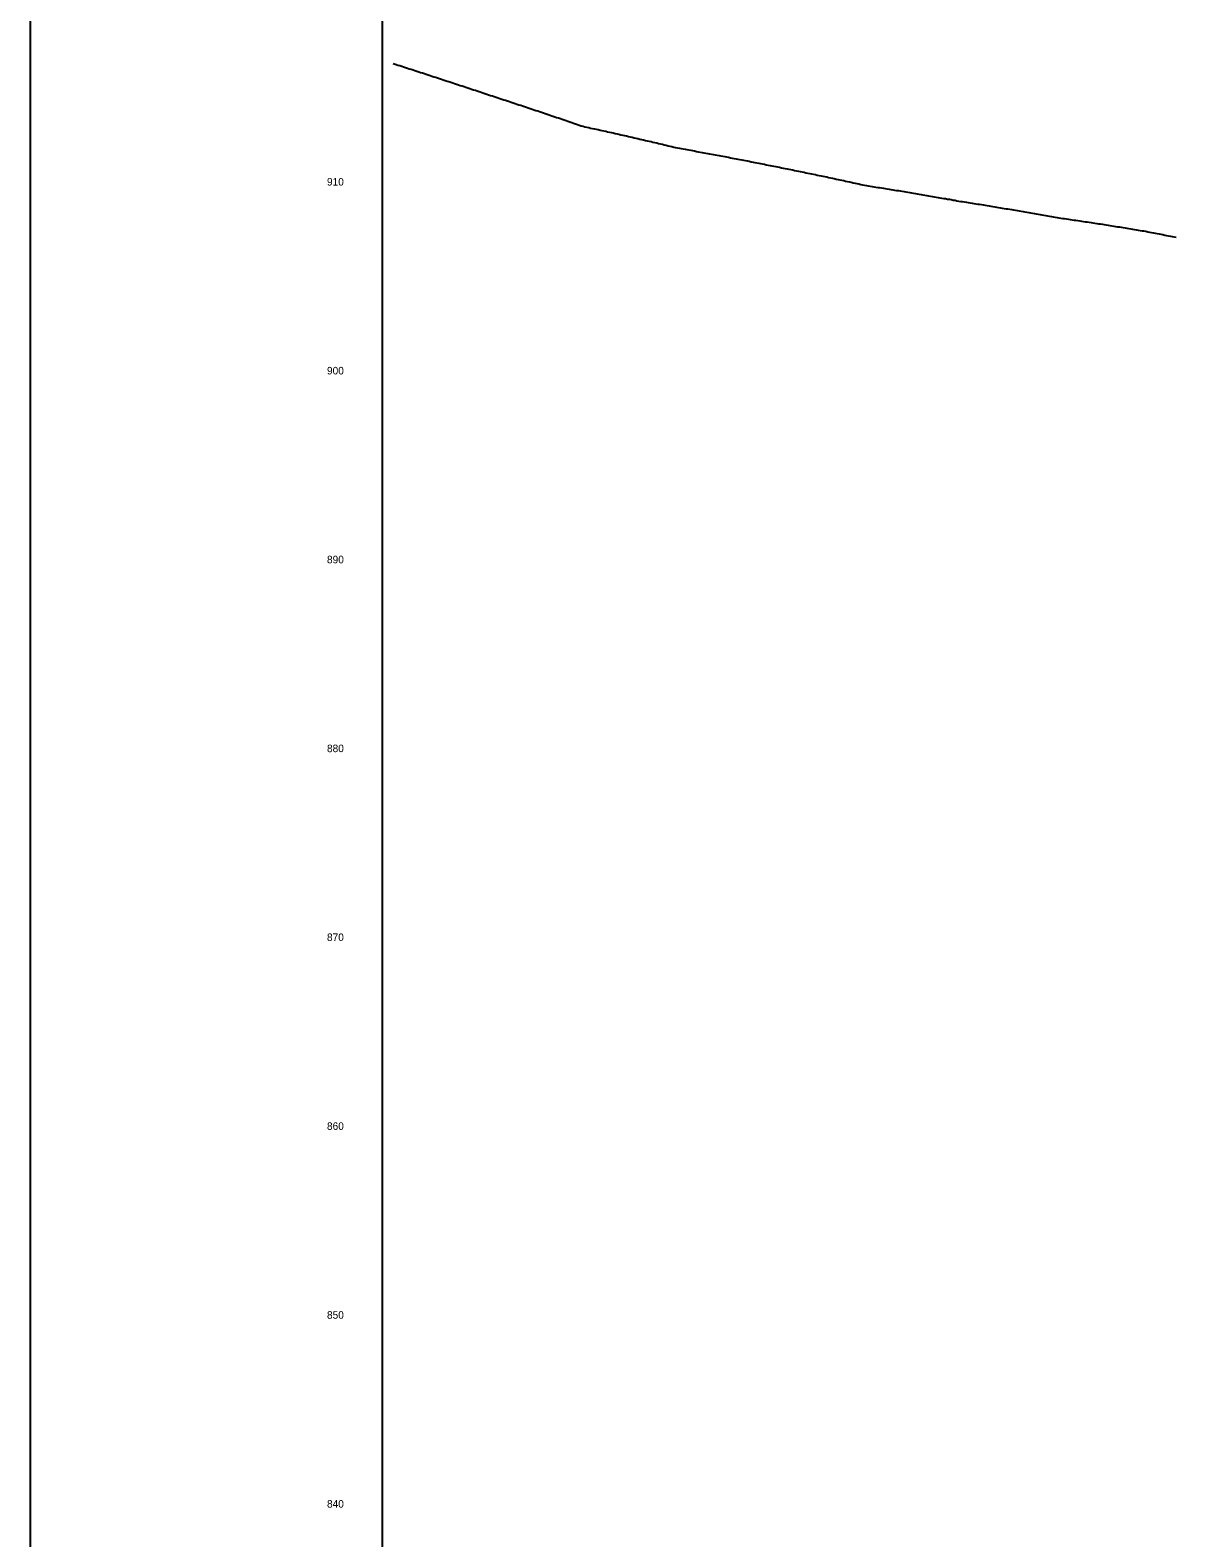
# Model space of a CAD drawing. Extents: x 1738393 to 1742179, y 1214897 to 1219897.
# Drawn here: x 1738393 to 1738999, y 1217783 to 1218581 of the extents above; entities that cross this region are included whole.
import ezdxf

# ---------------------------------------------------------------- set-up
doc = ezdxf.new("R2010")
doc.units = 0
for name, color, linetype in [('Default', 7, 'Continuous'), ('RD_DDB_ElevTX', 7, 'Continuous'), ('RD_DDB_Profile_EX', 7, 'Continuous'), ('RD_Sketch8', 7, 'Continuous')]:
    doc.layers.add(name, color=color, linetype=linetype)

msp = doc.modelspace()

# ---------------------------------------------------------------- linework, layer by layer
at = {"layer": 'Default'}
msp.add_line((1738579.37, 1217396.76), (1738579.37, 1219896.76), dxfattribs=at)
at = {"layer": 'RD_DDB_Profile_EX'}
for points in [[(1738585.11, 1218563.4), (1738585.58, 1218563.25), (1738586.58, 1218562.92), (1738587.58, 1218562.6), (1738588.58, 1218562.27), (1738589.58, 1218561.95), (1738590.58, 1218561.62), (1738591.58, 1218561.3), (1738592.58, 1218560.97), (1738593.58, 1218560.64), (1738594.58, 1218560.32), (1738595.58, 1218559.99), (1738596.58, 1218559.67), (1738597.58, 1218559.34), (1738598.58, 1218559.02), (1738599.58, 1218558.69), (1738600.58, 1218558.37), (1738601.58, 1218558.04), (1738602.58, 1218557.71), (1738603.58, 1218557.39), (1738604.58, 1218557.06), (1738605.58, 1218556.73), (1738606.58, 1218556.41), (1738607.58, 1218556.08), (1738608.58, 1218555.75), (1738609.58, 1218555.43), (1738610.58, 1218555.1), (1738611.58, 1218554.77), (1738612.58, 1218554.44), (1738613.58, 1218554.11), (1738614.58, 1218553.79), (1738615.58, 1218553.46), (1738616.58, 1218553.13), (1738617.58, 1218552.8), (1738618.58, 1218552.48), (1738619.58, 1218552.15), (1738620.58, 1218551.82), (1738621.58, 1218551.49), (1738622.58, 1218551.17), (1738623.58, 1218550.84), (1738624.58, 1218550.51), (1738625.58, 1218550.18), (1738626.58, 1218549.85), (1738627.58, 1218549.53), (1738628.58, 1218549.2), (1738629.58, 1218548.87), (1738630.58, 1218548.54), (1738631.58, 1218548.2), (1738632.58, 1218547.86), (1738633.58, 1218547.52), (1738634.58, 1218547.18), (1738635.58, 1218546.84), (1738636.58, 1218546.52), (1738637.58, 1218546.19), (1738638.58, 1218545.87), (1738639.58, 1218545.54), (1738640.58, 1218545.22), (1738641.58, 1218544.89), (1738642.58, 1218544.56), (1738643.58, 1218544.24), (1738644.58, 1218543.91), (1738645.58, 1218543.58), (1738646.58, 1218543.25), (1738647.58, 1218542.92), (1738648.58, 1218542.59), (1738649.58, 1218542.26), (1738650.58, 1218541.93), (1738651.58, 1218541.6), (1738652.58, 1218541.27), (1738653.58, 1218540.93), (1738654.58, 1218540.6), (1738655.58, 1218540.27), (1738656.58, 1218539.94), (1738657.58, 1218539.6), (1738658.58, 1218539.27), (1738659.58, 1218538.93), (1738660.58, 1218538.6), (1738661.58, 1218538.26), (1738662.58, 1218537.93), (1738663.58, 1218537.59), (1738664.58, 1218537.26), (1738665.58, 1218536.92), (1738666.58, 1218536.58), (1738667.58, 1218536.24), (1738668.58, 1218535.9), (1738669.58, 1218535.57), (1738670.58, 1218535.23), (1738671.58, 1218534.89), (1738672.58, 1218534.55), (1738673.58, 1218534.21), (1738674.58, 1218533.87), (1738675.58, 1218533.52), (1738676.58, 1218533.18), (1738677.58, 1218532.84), (1738678.58, 1218532.5), (1738679.58, 1218532.15), (1738680.58, 1218531.81), (1738681.58, 1218531.47), (1738682.58, 1218531.12), (1738683.58, 1218530.78), (1738684.58, 1218530.43)], [(1738684.58, 1218530.43), (1738685.58, 1218530.13), (1738686.58, 1218529.89), (1738687.58, 1218529.68), (1738688.58, 1218529.46), (1738689.58, 1218529.24), (1738690.58, 1218529.03), (1738691.58, 1218528.81), (1738692.58, 1218528.59), (1738693.58, 1218528.37), (1738694.58, 1218528.15), (1738695.58, 1218527.93), (1738696.58, 1218527.71), (1738697.58, 1218527.49), (1738698.58, 1218527.27), (1738699.58, 1218527.05), (1738700.58, 1218526.82), (1738701.58, 1218526.6), (1738702.58, 1218526.38), (1738703.58, 1218526.15), (1738704.58, 1218525.93), (1738705.58, 1218525.7), (1738706.58, 1218525.48), (1738707.58, 1218525.25), (1738708.58, 1218525.03), (1738709.58, 1218524.8), (1738710.58, 1218524.56), (1738711.58, 1218524.32), (1738712.58, 1218524.09), (1738713.58, 1218523.86), (1738714.58, 1218523.63), (1738715.58, 1218523.4), (1738716.58, 1218523.17), (1738717.58, 1218522.94), (1738718.58, 1218522.71), (1738719.58, 1218522.48), (1738720.58, 1218522.24), (1738721.58, 1218522.01), (1738722.58, 1218521.78), (1738723.58, 1218521.54), (1738724.58, 1218521.31), (1738725.58, 1218521.07), (1738726.58, 1218520.84), (1738727.58, 1218520.6), (1738728.58, 1218520.36), (1738729.58, 1218520.13), (1738730.58, 1218519.89), (1738731.58, 1218519.65), (1738732.58, 1218519.41), (1738733.58, 1218519.17), (1738734.58, 1218518.93), (1738735.58, 1218518.7), (1738736.58, 1218518.51), (1738737.58, 1218518.32), (1738738.58, 1218518.14), (1738739.58, 1218517.96), (1738740.58, 1218517.79), (1738741.58, 1218517.61), (1738742.58, 1218517.43), (1738743.58, 1218517.25), (1738744.58, 1218517.07), (1738745.58, 1218516.89), (1738746.58, 1218516.71), (1738747.58, 1218516.53), (1738748.58, 1218516.35), (1738749.58, 1218516.17), (1738750.58, 1218515.99), (1738751.58, 1218515.81), (1738752.58, 1218515.62), (1738753.58, 1218515.44), (1738754.58, 1218515.25), (1738755.58, 1218515.07), (1738756.58, 1218514.88), (1738757.58, 1218514.7), (1738758.58, 1218514.51), (1738759.58, 1218514.32), (1738760.58, 1218514.13), (1738761.58, 1218513.93), (1738762.58, 1218513.72), (1738763.58, 1218513.53), (1738764.58, 1218513.34), (1738765.58, 1218513.15), (1738766.58, 1218512.96), (1738767.58, 1218512.77), (1738768.58, 1218512.58), (1738769.58, 1218512.38), (1738770.58, 1218512.19), (1738771.58, 1218512), (1738772.58, 1218511.8), (1738773.58, 1218511.61), (1738774.58, 1218511.41), (1738775.58, 1218511.21), (1738776.58, 1218511.02), (1738777.58, 1218510.82), (1738778.58, 1218510.62), (1738779.58, 1218510.42), (1738780.58, 1218510.22), (1738781.58, 1218510.02), (1738782.58, 1218509.82), (1738783.58, 1218509.62), (1738784.58, 1218509.42)], [(1738784.58, 1218509.42), (1738785.58, 1218509.22), (1738786.58, 1218509.02), (1738787.58, 1218508.82), (1738788.58, 1218508.63), (1738789.58, 1218508.43), (1738790.58, 1218508.23), (1738791.58, 1218508.03), (1738792.58, 1218507.83), (1738793.58, 1218507.63), (1738794.58, 1218507.43), (1738795.58, 1218507.23), (1738796.58, 1218507.03), (1738797.58, 1218506.82), (1738798.58, 1218506.62), (1738799.58, 1218506.42), (1738800.58, 1218506.21), (1738801.58, 1218506.01), (1738802.58, 1218505.8), (1738803.58, 1218505.59), (1738804.58, 1218505.39), (1738805.58, 1218505.18), (1738806.58, 1218504.97), (1738807.58, 1218504.76), (1738808.58, 1218504.56), (1738809.58, 1218504.36), (1738810.58, 1218504.16), (1738811.58, 1218503.95), (1738812.58, 1218503.74), (1738813.58, 1218503.52), (1738814.58, 1218503.31), (1738815.58, 1218503.1), (1738816.58, 1218502.88), (1738817.58, 1218502.67), (1738818.58, 1218502.46), (1738819.58, 1218502.24), (1738820.58, 1218502.02), (1738821.58, 1218501.81), (1738822.58, 1218501.59), (1738823.58, 1218501.37), (1738824.58, 1218501.16), (1738825.58, 1218500.94), (1738826.58, 1218500.72), (1738827.58, 1218500.5), (1738828.58, 1218500.28), (1738829.58, 1218500.06), (1738830.58, 1218499.84), (1738831.58, 1218499.62), (1738832.58, 1218499.39), (1738833.58, 1218499.18), (1738834.58, 1218498.96), (1738835.58, 1218498.75), (1738836.58, 1218498.6), (1738837.58, 1218498.44), (1738838.58, 1218498.29), (1738839.58, 1218498.14), (1738840.58, 1218497.98), (1738841.58, 1218497.82), (1738842.58, 1218497.67), (1738843.58, 1218497.51), (1738844.58, 1218497.35), (1738845.58, 1218497.19), (1738846.58, 1218497.03), (1738847.58, 1218496.87), (1738848.58, 1218496.71), (1738849.58, 1218496.55), (1738850.58, 1218496.39), (1738851.58, 1218496.23), (1738852.58, 1218496.07), (1738853.58, 1218495.91), (1738854.58, 1218495.74), (1738855.58, 1218495.58), (1738856.58, 1218495.42), (1738857.58, 1218495.25), (1738858.58, 1218495.09), (1738859.58, 1218494.92), (1738860.58, 1218494.74), (1738861.58, 1218494.56), (1738862.58, 1218494.4), (1738863.58, 1218494.23), (1738864.58, 1218494.06), (1738865.58, 1218493.89), (1738866.58, 1218493.73), (1738867.58, 1218493.56), (1738868.58, 1218493.39), (1738869.58, 1218493.22), (1738870.58, 1218493.04), (1738871.58, 1218492.87), (1738872.58, 1218492.7), (1738873.58, 1218492.53), (1738874.58, 1218492.35), (1738875.58, 1218492.18), (1738876.58, 1218492), (1738877.58, 1218491.83), (1738878.58, 1218491.65), (1738879.58, 1218491.48), (1738880.58, 1218491.3), (1738881.58, 1218491.12), (1738882.58, 1218490.95), (1738883.58, 1218490.77), (1738884.58, 1218490.59)], [(1738884.58, 1218490.59), (1738885.58, 1218490.41), (1738886.58, 1218490.25), (1738887.58, 1218490.1), (1738888.58, 1218489.94), (1738889.58, 1218489.79), (1738890.58, 1218489.63), (1738891.58, 1218489.47), (1738892.58, 1218489.31), (1738893.58, 1218489.15), (1738894.58, 1218488.99), (1738895.58, 1218488.83), (1738896.58, 1218488.67), (1738897.58, 1218488.51), (1738898.58, 1218488.35), (1738899.58, 1218488.18), (1738900.58, 1218488.02), (1738901.58, 1218487.86), (1738902.58, 1218487.69), (1738903.58, 1218487.53), (1738904.58, 1218487.36), (1738905.58, 1218487.2), (1738906.58, 1218487.03), (1738907.58, 1218486.86), (1738908.58, 1218486.7), (1738909.58, 1218486.53), (1738910.58, 1218486.36), (1738911.58, 1218486.19), (1738912.58, 1218486.02), (1738913.58, 1218485.85), (1738914.58, 1218485.68), (1738915.58, 1218485.51), (1738916.58, 1218485.34), (1738917.58, 1218485.16), (1738918.58, 1218484.99), (1738919.58, 1218484.82), (1738920.58, 1218484.64), (1738921.58, 1218484.47), (1738922.58, 1218484.29), (1738923.58, 1218484.12), (1738924.58, 1218483.94), (1738925.58, 1218483.76), (1738926.58, 1218483.59), (1738927.58, 1218483.41), (1738928.58, 1218483.23), (1738929.58, 1218483.05), (1738930.58, 1218482.87), (1738931.58, 1218482.69), (1738932.58, 1218482.51), (1738933.58, 1218482.33), (1738934.58, 1218482.15), (1738935.58, 1218481.97), (1738936.58, 1218481.83), (1738937.58, 1218481.68), (1738938.58, 1218481.54), (1738939.58, 1218481.4), (1738940.58, 1218481.26), (1738941.58, 1218481.11), (1738942.58, 1218480.97), (1738943.58, 1218480.82), (1738944.58, 1218480.68), (1738945.58, 1218480.53), (1738946.58, 1218480.38), (1738947.58, 1218480.24), (1738948.58, 1218480.09), (1738949.58, 1218479.94), (1738950.58, 1218479.79), (1738951.58, 1218479.64), (1738952.58, 1218479.49), (1738953.58, 1218479.34), (1738954.58, 1218479.19), (1738955.58, 1218479.04), (1738956.58, 1218478.89), (1738957.58, 1218478.74), (1738958.58, 1218478.59), (1738959.58, 1218478.43), (1738960.58, 1218478.26), (1738961.58, 1218478.1), (1738962.58, 1218477.94), (1738963.58, 1218477.79), (1738964.58, 1218477.63), (1738965.58, 1218477.47), (1738966.58, 1218477.31), (1738967.58, 1218477.16), (1738968.58, 1218477), (1738969.58, 1218476.84), (1738970.58, 1218476.68), (1738971.58, 1218476.52), (1738972.58, 1218476.35), (1738973.58, 1218476.19), (1738974.58, 1218476.03), (1738975.58, 1218475.87), (1738976.58, 1218475.7), (1738977.58, 1218475.54), (1738978.58, 1218475.37), (1738979.58, 1218475.21), (1738980.58, 1218475.04), (1738981.58, 1218474.87), (1738982.58, 1218474.71), (1738983.58, 1218474.54), (1738984.58, 1218474.35)], [(1738984.58, 1218474.35), (1738985.58, 1218474.14), (1738986.58, 1218473.95), (1738987.58, 1218473.76), (1738988.58, 1218473.56), (1738989.58, 1218473.37), (1738990.58, 1218473.18), (1738991.58, 1218472.98), (1738992.58, 1218472.79), (1738993.58, 1218472.59), (1738994.58, 1218472.39), (1738995.58, 1218472.2), (1738996.58, 1218472), (1738997.58, 1218471.8), (1738998.58, 1218471.6), (1738999.58, 1218471.4)]]:
    msp.add_lwpolyline(points, dxfattribs=at)
at = {"layer": 'RD_Sketch8'}
msp.add_lwpolyline([(1738392.83, 1217035.51), (1741992.83, 1217035.51), (1741992.83, 1219235.51), (1738392.83, 1219235.51)], close=True, dxfattribs=at)

# ---------------------------------------------------------------- texts
at = {"layer": 'RD_DDB_ElevTX'}
for s, p in [('910', (1738550, 1218498.76)), ('910', (1738550, 1218498.76)), ('910', (1738550, 1218498.76)), ('900', (1738550, 1218398.76)), ('900', (1738550, 1218398.76)), ('900', (1738550, 1218398.76)), ('890', (1738550, 1218298.76)), ('890', (1738550, 1218298.76)), ('890', (1738550, 1218298.76)), ('880', (1738550, 1218198.76)), ('880', (1738550, 1218198.76)), ('880', (1738550, 1218198.76)), ('870', (1738550, 1218098.76)), ('870', (1738550, 1218098.76)), ('870', (1738550, 1218098.76)), ('860', (1738550, 1217998.76)), ('860', (1738550, 1217998.76)), ('860', (1738550, 1217998.76)), ('850', (1738550, 1217898.76)), ('850', (1738550, 1217898.76)), ('850', (1738550, 1217898.76)), ('840', (1738550, 1217798.76)), ('840', (1738550, 1217798.76)), ('840', (1738550, 1217798.76))]:
    msp.add_text(s, height=4, dxfattribs=at).set_placement(p)

doc.saveas('drawing.dxf')
